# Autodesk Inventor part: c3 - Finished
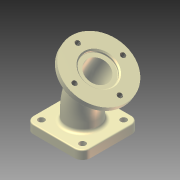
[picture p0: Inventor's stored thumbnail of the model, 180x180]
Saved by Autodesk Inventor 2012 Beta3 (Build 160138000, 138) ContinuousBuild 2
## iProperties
Created: 2010-11
Part Number: c3 - Finished
Material: Cast Iron
Document SubType Name: Modeling
Designer: Beta-8540w
Density: 7.25 g/cm^3
Mass: 1087.5 g
Surface Area: 260 cm^2
Volume: 150 cm^3
Author: Beta-8540w
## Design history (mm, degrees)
sketch "Sketch1"
  geometry: L1 (-50, -50)-(50, -50); L2 (50, -50)-(50, 50); L3 (50, 50)-(-50, 50); L4 (-50, 50)-(-50, -50); C1 r 20 at (0, 0); C2 r 28 at (0, 0); 3 further points
  constraints: 8 end point, 3 perpendicular, 2 centre point, 2 coincident, 2 midpoint, 1 horizontal, 1 horizontal alignment, 1 parallel, 1 vertical alignment
  dimensions: "Width" = 100 distance of L1.start L1.end; "d6" = 40 diameter of C1; "d7" = 8 radial gap between concentric circles of C2 C1
extrude "Extrusion1" new body sketch "Sketch1" distance "d3" = 15; taper "d4" = 0 deg
fillet "Fillet1" dims "d5" = 14
sketch "Sketch2"
  geometry: L1 (0, 0)-(0, 30); L2 (-13.397, 80)-(-28.397, 105.981); A1 r 100 centre (-100, 30) between (0, 30) and (-13.397, 80)
  constraints: 4 end point, 2 point on circle, 2 tangent, 1 centre point, 1 vertical
  dimensions: "d8" = 30 distance of L1.start L1.end; "d9" = 100 radius of A1; "d10" = 30 distance of L2.start L2.end; "d11" = 30 deg angle of L2 L1
sketch "Sketch3"
  geometry: L1 (-13.397, 80)-(-28.397, 105.981) reference; L2 (-28.397, 105.981)-(-76.029, 78.481); L3 (-76.029, 78.481)-(-71.029, 69.821); L4 (-71.029, 69.821)-(-23.397, 97.321); L5 (-23.397, 97.321)-(-28.397, 105.981); 1 further point
  constraints: 8 end point, 2 parallel, 2 perpendicular
  dimensions: "d16" = 10 distance of L3.end L2.end; "d17" = 110 diameter of L3 L5
revolve "Revolution1" sketch "Sketch3" stored, may be unused: angle "d18" = 90 deg
sweep "Sweep1" dims "d19" = 0
sweep "Sweep2" dims "d20" = 0
sketch "Sketch4"
  geometry: C1 r 20 at (0, 0) reference; C2 r 55 at (0, 0) reference; C3 r 27.5 at (0, 0); 1 further point
  constraints: 1 centre point, 1 coincident
  dimensions: "d21" = 55 diameter of C3
extrude "Extrusion2" cut sketch "Sketch4" distance "d22" = 5; taper "d23" = 0 deg
sketch "Sketch5"
  geometry: L1 (0, 0)-(0, 9.711); L2 (-25, 0)-(-27, 0); L3 (-27, 0)-(-27, 1.5); L4 (-26.5, 2)-(-25.5, 2); L5 (-25, 1.5)-(-25, 0); A1 r 0.5 centre (-25.5, 1.5) between (-25, 1.5) and (-25.5, 2); A2 r 0.5 centre (-26.5, 1.5) between (-26.5, 2) and (-27, 1.5); 1 further point
  constraints: 10 end point, 4 point on circle, 4 tangent, 3 point on line, 2 centre point, 2 parallel, 1 equal radius, 1 horizontal, 1 perpendicular, 1 vertical
  dimensions: "d24" = 2 distance of L2.start L2.end; "d25" = 2 distance of point (-25, 2) L2.start; "d26" = 50 diameter of L5 L1; "d27" = 0.5 radius of A1
revolve "Revolution2" sketch "Sketch5" stored, may be unused: angle "d28" = 90 deg
hole "Hole1" diameter "d31" = 11; stored, may be unused: countersink angle "d35" = 7.5 deg, drill point angle "d37" = 118 deg; dims "d29" = 10, "d30" = 10, "d32" = 6, "d33" = 28, "d34" = 2, "d36" = 8
pattern_circular "Circular Pattern1" dims angle "d39" = 360 deg
sketch "Hole Sketch" dims "d41" = 85
  geometry: L1 (0, -42.5)-(-42.5, 0); L2 (-42.5, 0)-(0, 42.5); L3 (0, 42.5)-(42.5, 0); L4 (42.5, 0)-(0, -42.5); C1 r 27.5 at (0, 0) reference; 2 further points
  constraints: 8 end point, 2 coincident, 2 horizontal alignment, 11 other
hole "Hole2" sketch "Hole Sketch" at (0, -42.5), (-42.5, 0), (0, 42.5), (42.5, 0) diameter "d42" = 8.376; stored, may be unused: countersink angle "d46" = 90 deg, drill point angle "d48" = 118 deg; dims "d43" = 6, "d44" = 4, "d45" = 2, "d47" = 8
fillet "Fillet2" dims "d49" = 6, "d50" = 2, "d51" = 0.5
chamfer "Chamfer1" distance "d52" = 2; stored, may be unused: second distance "d53" = 2, angle "d54" = 45 deg
chamfer "Chamfer2" distance "d55" = 2; stored, may be unused: second distance "d56" = 4, angle "d57" = 45 deg
body "Solid1"
